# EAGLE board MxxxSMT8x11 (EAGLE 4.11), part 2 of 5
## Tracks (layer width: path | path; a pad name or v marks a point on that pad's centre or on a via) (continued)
D1  (via drill 0.61) (continued)
  Top 0.254: E16.4 94.23,12.7 96.27,10.67 96.27,9.14 97.54,9.14 E19.14 99.31,9.14 101.35,9.14 101.35,15.49 v100.33,16.51 | v80.01,15.24 81.03,15.24 E13.6 82.8,15.24 v84.07,16.51 | E10.9 65.02,15.24 v66.04,15.24 65.79,15.49 v65.79,19.56 | 46.74,12.45 50.04,12.45 50.04,11.94 50.55,11.43 E7.12 52.32,11.43 53.59,12.7 53.59,15.24 v56.13,17.78 | 46.74,12.45 44.7,12.45 E4.4 | v14.99,13.97 13.97,13.97 U$1.D1 | E1.5 30.23,13.97 v29.21,13.97 29.21,14.22 v29.21,17.27 | v46.74,17.27 46.74,12.45
  Bottom 0.254: v66.04,15.24 v80.01,15.24 | v84.07,16.51 v100.33,16.51 | v14.99,13.97 v29.21,13.97 | v46.74,17.27 46.48,17.02 29.46,17.02 v29.21,17.27 | v65.79,19.56 65.28,19.05 57.4,19.05 v56.13,17.78
D2  (via drill 0.61)
  Top 0.254: v59.69,8.64 59.69,11.18 58.67,11.18 E7.3 56.9,11.18 v55.88,11.18 | v68.58,8.64 69.6,8.64 E10.1 | v80.01,8.89 81.03,8.89 E13.1 82.8,8.64 82.8,5.08 100.08,5.08 101.85,6.86 101.85,13.72 103.89,13.72 E19.5 | v85.09,12.19 85.09,12.45 86.11,12.45 E16.11 | v29.21,12.7 30.23,12.7 E1.4 32,12.7 32.51,12.19 32.51,10.41 36.58,10.41 E4.13 38.35,10.41 38.35,10.67 v39.37,10.67
  Bottom 0.254: v59.69,8.64 v68.58,8.64 68.83,8.89 v80.01,8.89 80.26,9.14 82.04,9.14 v85.09,12.19 | v29.21,12.7 13.97,12.7 U$1.D2 | v55.88,11.18 55.37,10.67 v39.37,10.67
D3  (via drill 0.61)
  Top 0.254: v59.69,74.68 59.69,77.22 58.67,77.22 E25.3 56.9,77.22 v55.88,77.22 | v68.58,74.68 69.6,74.68 E28.1 | v80.01,74.93 81.03,74.93 E31.1 82.8,74.68 82.8,71.12 100.08,71.12 101.85,72.9 101.85,79.76 103.89,79.76 E40.5 | v85.09,78.23 85.09,78.49 86.11,78.49 E37.11 | v29.21,78.74 30.23,78.74 E34.4 32,78.74 32.51,78.23 32.51,76.45 36.58,76.45 E22.13 38.35,76.45 38.35,76.71 v39.37,76.71
  Bottom 0.254: v59.69,74.68 v68.58,74.68 68.83,74.93 v80.01,74.93 80.26,75.18 82.04,75.18 v85.09,78.23 | v29.21,78.74 13.97,78.74 U$6.D2 | v55.88,77.22 55.37,76.71 v39.37,76.71
D4  (via drill 0.61)
  Top 0.254: E37.4 94.23,78.74 96.27,76.71 96.27,75.18 97.54,75.18 E40.14 99.31,75.18 101.35,75.18 101.35,81.53 v100.33,82.55 | v80.01,81.28 81.03,81.28 E31.6 82.8,81.28 v84.07,82.55 | E28.9 65.02,81.28 v66.04,81.28 65.79,81.53 v65.79,85.6 | 46.74,78.49 50.04,78.49 50.04,77.98 50.55,77.47 E25.12 52.32,77.47 53.59,78.74 53.59,81.28 v56.13,83.82 | 46.74,78.49 44.7,78.49 E22.4 | v14.99,80.01 13.97,80.01 U$6.D1 | E34.5 30.23,80.01 v29.21,80.01 29.21,80.26 v29.21,83.31 | v46.74,83.31 46.74,78.49
  Bottom 0.254: v66.04,81.28 v80.01,81.28 | v84.07,82.55 v100.33,82.55 | v14.99,80.01 v29.21,80.01 | v46.74,83.31 46.48,83.06 29.46,83.06 v29.21,83.31 | v65.79,85.6 65.28,85.09 57.4,85.09 v56.13,83.82
D5  (via drill 0.61)
  Top 0.254: v59.69,140.72 59.69,143.26 58.67,143.26 E46.3 56.9,143.26 v55.88,143.26 | v68.58,140.72 69.6,140.72 E49.1 | v80.01,140.97 81.03,140.97 E52.1 82.8,140.72 82.8,137.16 100.08,137.16 101.85,138.94 101.85,145.8 103.89,145.8 E61.5 | v85.09,144.27 85.09,144.53 86.11,144.53 E58.11 | v29.21,144.78 30.23,144.78 E55.4 32,144.78 32.51,144.27 32.51,142.49 36.58,142.49 E43.13 38.35,142.49 38.35,142.75 v39.37,142.75
  Bottom 0.254: v59.69,140.72 v68.58,140.72 68.83,140.97 v80.01,140.97 80.26,141.22 82.04,141.22 v85.09,144.27 | v29.21,144.78 13.97,144.78 U$9.D2 | v55.88,143.26 55.37,142.75 v39.37,142.75
D6  (via drill 0.61)
  Top 0.254: E58.4 94.23,144.78 96.27,142.75 96.27,141.22 97.54,141.22 E61.14 99.31,141.22 101.35,141.22 101.35,147.57 v100.33,148.59 | v80.01,147.32 81.03,147.32 E52.6 82.8,147.32 v84.07,148.59 | E49.9 65.02,147.32 v66.04,147.32 65.79,147.57 v65.79,151.64 | 46.74,144.53 50.04,144.53 50.04,144.02 50.55,143.51 E46.12 52.32,143.51 53.59,144.78 53.59,147.32 v56.13,149.86 | 46.74,144.53 44.7,144.53 E43.4 | v14.99,146.05 13.97,146.05 U$9.D1 | E55.5 30.23,146.05 v29.21,146.05 29.21,146.3 v29.21,149.35 | v46.74,149.35 46.74,144.53
  Bottom 0.254: v66.04,147.32 v80.01,147.32 | v84.07,148.59 v100.33,148.59 | v14.99,146.05 v29.21,146.05 | v46.74,149.35 46.48,149.1 29.46,149.1 v29.21,149.35 | v65.79,151.64 65.28,151.13 57.4,151.13 v56.13,149.86
D7  (via drill 0.61)
  Top 0.254: v196.85,185.67 196.85,183.13 197.87,183.13 E67.3 199.64,183.13 v200.66,183.13 | v187.96,185.67 186.94,185.67 E70.1 | v176.53,185.42 175.51,185.42 E73.1 173.74,185.67 173.74,189.23 156.46,189.23 154.69,187.45 154.69,180.59 152.65,180.59 E82.5 | v171.45,182.12 171.45,181.86 170.43,181.86 E79.11 | v227.33,181.61 226.31,181.61 E76.4 224.54,181.61 224.03,182.12 224.03,183.9 219.96,183.9 E64.13 218.19,183.9 218.19,183.64 v217.17,183.64
  Bottom 0.254: v196.85,185.67 v187.96,185.67 187.71,185.42 v176.53,185.42 176.28,185.17 174.5,185.17 v171.45,182.12 | v227.33,181.61 242.57,181.61 U$12.D2 | v200.66,183.13 201.17,183.64 v217.17,183.64
D8  (via drill 0.61)
  Top 0.254: E79.4 162.31,181.61 160.27,183.64 160.27,185.17 159,185.17 E82.14 157.23,185.17 155.19,185.17 155.19,178.82 v156.21,177.8 | v176.53,179.07 175.51,179.07 E73.6 173.74,179.07 v172.47,177.8 | E70.9 191.52,179.07 v190.5,179.07 190.75,178.82 v190.75,174.75 | 209.8,181.86 206.5,181.86 206.5,182.37 205.99,182.88 E67.12 204.22,182.88 202.95,181.61 202.95,179.07 v200.41,176.53 | 209.8,181.86 211.84,181.86 E64.4 | v241.55,180.34 242.57,180.34 U$12.D1 | E76.5 226.31,180.34 v227.33,180.34 227.33,180.09 v227.33,177.04 | 209.8,181.86 v209.8,177.04
  Bottom 0.254: v176.53,179.07 v190.5,179.07 | v156.21,177.8 v172.47,177.8 | v227.33,180.34 v241.55,180.34 | v209.8,177.04 210.06,177.29 227.08,177.29 v227.33,177.04 | v190.75,174.75 191.26,175.26 199.14,175.26 v200.41,176.53
D9  (via drill 0.61)
  Top 0.254: v196.85,119.63 196.85,117.09 197.87,117.09 E88.3 199.64,117.09 v200.66,117.09 | v187.96,119.63 186.94,119.63 E91.1 | v176.53,119.38 175.51,119.38 E94.1 173.74,119.63 173.74,123.19 156.46,123.19 154.69,121.41 154.69,114.55 152.65,114.55 E103.5 | v171.45,116.08 171.45,115.82 170.43,115.82 E100.11 | v227.33,115.57 226.31,115.57 E97.4 224.54,115.57 224.03,116.08 224.03,117.86 219.96,117.86 E85.13 218.19,117.86 218.19,117.6 v217.17,117.6
  Bottom 0.254: v196.85,119.63 v187.96,119.63 187.71,119.38 v176.53,119.38 176.28,119.13 174.5,119.13 v171.45,116.08 | v227.33,115.57 242.57,115.57 U$15.D2 | v200.66,117.09 201.17,117.6 v217.17,117.6
D10  (via drill 0.61)
  Top 0.254: E100.4 162.31,115.57 160.27,117.6 160.27,119.13 159,119.13 E103.14 157.23,119.13 155.19,119.13 155.19,112.78 v156.21,111.76 | v176.53,113.03 175.51,113.03 E94.6 173.74,113.03 v172.47,111.76 | E91.9 191.52,113.03 v190.5,113.03 190.75,112.78 v190.75,108.71 | 209.8,115.82 206.5,115.82 206.5,116.33 205.99,116.84 E88.12 204.22,116.84 202.95,115.57 202.95,113.03 v200.41,110.49 | 209.8,115.82 211.84,115.82 E85.4 | v241.55,114.3 242.57,114.3 U$15.D1 | E97.5 226.31,114.3 v227.33,114.3 227.33,114.05 v227.33,111 | 209.8,115.82 v209.8,111
  Bottom 0.254: v176.53,113.03 v190.5,113.03 | v156.21,111.76 v172.47,111.76 | v227.33,114.3 v241.55,114.3 | v209.8,111 210.06,111.25 227.08,111.25 v227.33,111 | v190.75,108.71 191.26,109.22 199.14,109.22 v200.41,110.49
D11  (via drill 0.61)
  Top 0.254: v196.85,53.59 196.85,51.05 197.87,51.05 E109.3 199.64,51.05 v200.66,51.05 | v187.96,53.59 186.94,53.59 E112.1 | v176.53,53.34 175.51,53.34 E115.1 173.74,53.59 173.74,57.15 156.46,57.15 154.69,55.37 154.69,48.51 152.65,48.51 E124.5 | v171.45,50.04 171.45,49.78 170.43,49.78 E121.11 | v227.33,49.53 226.31,49.53 E118.4 224.54,49.53 224.03,50.04 224.03,51.82 219.96,51.82 E106.13 218.19,51.82 218.19,51.56 v217.17,51.56
  Bottom 0.254: v196.85,53.59 v187.96,53.59 187.71,53.34 v176.53,53.34 176.28,53.09 174.5,53.09 v171.45,50.04 | v227.33,49.53 242.57,49.53 U$18.D2 | v200.66,51.05 201.17,51.56 v217.17,51.56
D12  (via drill 0.61)
  Top 0.254: E121.4 162.31,49.53 160.27,51.56 160.27,53.09 159,53.09 E124.14 157.23,53.09 155.19,53.09 155.19,46.74 v156.21,45.72 | v176.53,46.99 175.51,46.99 E115.6 173.74,46.99 v172.47,45.72 | E112.9 191.52,46.99 v190.5,46.99 190.75,46.74 v190.75,42.67 | 209.8,49.78 206.5,49.78 206.5,50.29 205.99,50.8 E109.12 204.22,50.8 202.95,49.53 202.95,46.99 v200.41,44.45 | 209.8,49.78 211.84,49.78 E106.4 | v241.55,48.26 242.57,48.26 U$18.D1 | E118.5 226.31,48.26 v227.33,48.26 227.33,48.01 v227.33,44.96 | 209.8,49.78 v209.8,44.96
  Bottom 0.254: v190.5,46.99 v176.53,46.99 | v172.47,45.72 v156.21,45.72 | v227.33,48.26 v241.55,48.26 | v209.8,44.96 210.06,45.21 227.08,45.21 v227.33,44.96 | v190.75,42.67 191.26,43.18 199.14,43.18 v200.41,44.45
E1  (via drill 0.61)
  Top 0.254: v91.44,14.22 92.46,14.22 E16.5 | v100.33,13.46 100.08,13.21 100.08,12.19 99.31,11.43 E19.12 | v80.01,16.51 79.25,17.27 v79.25,18.29 | v64.52,20.07 64.52,16.76 E10.8 63.25,16.51 v62.23,16.51 | v45.72,14.22 44.7,14.22 E4.5 | v49.28,14.22 50.8,14.22 E7.10 | v35.56,11.68 33.02,14.22 33.02,15.24 32,15.24 E1.6 | v16.76,10.16 16.26,10.67 16.26,14.22 15.24,15.24 | 15.24,15.24 13.72,16.76 U$1.E1 | 15.24,15.24 v16.26,16.26
  Bottom 0.254: v100.33,13.46 99.31,14.48 91.69,14.48 v91.44,14.22 91.19,14.48 84.84,14.48 82.8,16.51 v80.01,16.51 | v79.25,18.29 77.22,20.32 66.29,20.32 66.04,20.57 65.02,20.57 v64.52,20.07 | v35.56,11.68 33.53,9.65 23.88,9.65 23.88,9.14 17.78,9.14 v16.76,10.16 | v16.26,16.26 23.88,16.26 23.88,15.75 38.61,15.75 40.13,14.22 v45.72,14.22 v49.28,14.22 49.53,14.48 50.8,15.75 61.47,15.75 v62.23,16.51
E2  (via drill 0.61)
  Top 0.254: v80.01,10.16 81.03,10.16 E13.2 82.8,10.16 83.31,10.67 83.31,11.18 86.11,11.18 E16.12 87.88,11.43 88.65,12.19 88.65,12.7 90.93,14.99 90.93,17.78 90.68,18.03 90.68,22.1 90.93,22.35 90.93,24.13 92.96,24.13 93.98,23.11 93.98,19.56 97.03,16.51 97.03,14.22 97.54,14.22 E19.10 | E10.2 69.6,10.16 v68.58,10.16 68.33,10.41 67.31,11.43 v67.31,12.19 | v39.37,11.94 39.37,11.68 38.35,11.68 E4.12 | v55.88,12.45 56.9,12.45 E7.4 | v22.86,15.24 23.88,15.24 E1.9
  Bottom 0.254: v68.58,10.16 v80.01,10.16 | U$1.E2 13.97,16.26 14.99,16.26 16,15.24 v22.86,15.24 29.21,15.24 30.48,13.97 37.34,13.97 v39.37,11.94 39.62,12.19 55.63,12.19 v55.88,12.45 56.13,12.19 v67.31,12.19
E3  (via drill 0.61)
  Top 0.254: v80.01,76.2 81.03,76.2 E31.2 82.8,76.2 83.31,76.71 83.31,77.22 86.11,77.22 E37.12 87.88,77.47 88.65,78.23 88.65,78.74 90.93,81.03 90.93,83.82 90.68,84.07 90.68,88.14 90.93,88.39 90.93,90.17 92.96,90.17 93.98,89.15 93.98,85.6 97.03,82.55 97.03,80.26 97.54,80.26 E40.10 | E28.2 69.6,76.2 v68.58,76.2 68.33,76.45 67.31,77.47 v67.31,78.23 | v39.37,77.98 39.37,77.72 38.35,77.72 E22.12 | v55.88,78.49 56.9,78.49 E25.4 | v22.86,81.28 23.88,81.28 E34.9
  Bottom 0.254: v68.58,76.2 v80.01,76.2 | U$6.E2 13.97,82.3 14.99,82.3 16,81.28 v22.86,81.28 29.21,81.28 30.48,80.01 37.34,80.01 v39.37,77.98 39.62,78.23 55.63,78.23 v55.88,78.49 56.13,78.23 v67.31,78.23
E4  (via drill 0.61)
  Top 0.254: v91.44,80.26 92.46,80.26 E37.5 | v100.33,79.5 100.08,79.25 100.08,78.23 99.31,77.47 E40.12 | v80.01,82.55 79.25,83.31 v79.25,84.33 | v64.52,86.11 64.52,82.8 E28.8 63.25,82.55 v62.23,82.55 | v45.72,80.26 44.7,80.26 E22.5 | v49.28,80.26 50.8,80.26 E25.10 | v35.56,77.72 33.02,80.26 33.02,81.28 32,81.28 E34.6 | v16.76,76.2 16.26,76.71 16.26,80.26 15.24,81.28 | 15.24,81.28 13.72,82.8 U$6.E1 | 15.24,81.28 v16.26,82.3
  Bottom 0.254: v100.33,79.5 99.31,80.52 91.69,80.52 v91.44,80.26 91.19,80.52 84.84,80.52 82.8,82.55 v80.01,82.55 | v79.25,84.33 77.22,86.36 66.29,86.36 66.04,86.61 65.02,86.61 v64.52,86.11 | v35.56,77.72 33.53,75.69 23.88,75.69 23.88,75.18 17.78,75.18 v16.76,76.2 | v16.26,82.3 23.88,82.3 23.88,81.79 38.61,81.79 40.13,80.26 v45.72,80.26 v49.28,80.26 49.53,80.52 50.8,81.79 61.47,81.79 v62.23,82.55
E5  (via drill 0.61)
  Top 0.254: v80.01,142.24 81.03,142.24 E52.2 82.8,142.24 83.31,142.75 83.31,143.26 86.11,143.26 E58.12 87.88,143.51 88.65,144.27 88.65,144.78 90.93,147.07 90.93,149.86 90.68,150.11 90.68,154.18 90.93,154.43 90.93,156.21 92.96,156.21 93.98,155.19 93.98,151.64 97.03,148.59 97.03,146.3 97.54,146.3 E61.10 | E49.2 69.6,142.24 v68.58,142.24 68.33,142.49 67.31,143.51 v67.31,144.27 | v39.37,144.02 39.37,143.76 38.35,143.76 E43.12 | v55.88,144.53 56.9,144.53 E46.4 | v22.86,147.32 23.88,147.32 E55.9
  Bottom 0.254: v68.58,142.24 v80.01,142.24 | U$9.E2 13.97,148.34 14.99,148.34 16,147.32 v22.86,147.32 29.21,147.32 30.48,146.05 37.34,146.05 v39.37,144.02 39.62,144.27 55.63,144.27 v55.88,144.53 56.13,144.27 v67.31,144.27
E6  (via drill 0.61)
  Top 0.254: v91.44,146.3 92.46,146.3 E58.5 | v100.33,145.54 100.08,145.29 100.08,144.27 99.31,143.51 E61.12 | v80.01,148.59 79.25,149.35 v79.25,150.37 | v64.52,152.15 64.52,148.84 E49.8 63.25,148.59 v62.23,148.59 | v45.72,146.3 44.7,146.3 E43.5 | v49.28,146.3 50.8,146.3 E46.10 | v35.56,143.76 33.02,146.3 33.02,147.32 32,147.32 E55.6 | v16.76,142.24 16.26,142.75 16.26,146.3 15.24,147.32 | 15.24,147.32 13.72,148.84 U$9.E1 | 15.24,147.32 v16.26,148.34
  Bottom 0.254: v100.33,145.54 99.31,146.56 91.69,146.56 v91.44,146.3 91.19,146.56 84.84,146.56 82.8,148.59 v80.01,148.59 | v79.25,150.37 77.22,152.4 66.29,152.4 66.04,152.65 65.02,152.65 v64.52,152.15 | v35.56,143.76 33.53,141.73 23.88,141.73 23.88,141.22 17.78,141.22 v16.76,142.24 | v16.26,148.34 23.88,148.34 23.88,147.83 38.61,147.83 40.13,146.3 v45.72,146.3 v49.28,146.3 49.53,146.56 50.8,147.83 61.47,147.83 v62.23,148.59
E7  (via drill 0.61)
  Top 0.254: v176.53,184.15 175.51,184.15 E73.2 173.74,184.15 173.23,183.64 173.23,183.13 170.43,183.13 E79.12 168.66,182.88 167.89,182.12 167.89,181.61 165.61,179.32 165.61,176.53 165.86,176.28 165.86,172.21 165.61,171.96 165.61,170.18 163.58,170.18 162.56,171.2 162.56,174.75 159.51,177.8 159.51,180.09 159,180.09 E82.10 | E70.2 186.94,184.15 v187.96,184.15 188.21,183.9 189.23,182.88 v189.23,182.12 | v217.17,182.37 217.17,182.63 218.19,182.63 E64.12 | v200.66,181.86 199.64,181.86 E67.4 | v233.68,179.07 232.66,179.07 E76.9
  Bottom 0.254: v176.53,184.15 v187.96,184.15 | U$12.E2 242.57,178.05 241.55,178.05 240.54,179.07 v233.68,179.07 227.33,179.07 226.06,180.34 219.2,180.34 v217.17,182.37 216.92,182.12 200.91,182.12 v200.66,181.86 200.41,182.12 v189.23,182.12
E8  (via drill 0.61)
  Top 0.254: v165.1,180.09 164.08,180.09 E79.5 | v156.21,180.85 156.46,181.1 156.46,182.12 157.23,182.88 E82.12 | v176.53,177.8 177.29,177.04 v177.29,176.02 | v192.02,174.24 192.02,177.55 E70.8 193.29,177.8 v194.31,177.8 | v210.82,180.09 211.84,180.09 E64.5 | v207.26,180.09 205.74,180.09 E67.10 | v220.98,182.63 223.52,180.09 223.52,179.07 224.54,179.07 E76.6 | v239.78,184.15 240.28,183.64 240.28,180.09 241.3,179.07 | 241.3,179.07 242.82,177.55 U$12.E1 | v240.28,178.05 241.3,179.07
  Bottom 0.254: v156.21,180.85 157.23,179.83 164.85,179.83 v165.1,180.09 165.35,179.83 171.7,179.83 173.74,177.8 v176.53,177.8 | v177.29,176.02 179.32,173.99 190.25,173.99 190.5,173.74 191.52,173.74 v192.02,174.24 | v220.98,182.63 223.01,184.66 232.66,184.66 232.66,185.17 238.76,185.17 v239.78,184.15 | v240.28,178.05 232.66,178.05 232.66,178.56 217.93,178.56 216.41,180.09 v210.82,180.09 v207.26,180.09 207.01,179.83 205.74,178.56 195.07,178.56 v194.31,177.8
E9  (via drill 0.61)
  Top 0.254: v176.53,118.11 175.51,118.11 E94.2 173.74,118.11 173.23,117.6 173.23,117.09 170.43,117.09 E100.12 168.66,116.84 167.89,116.08 167.89,115.57 165.61,113.28 165.61,110.49 165.86,110.24 165.86,106.17 165.61,105.92 165.61,104.14 163.58,104.14 162.56,105.16 162.56,108.71 159.51,111.76 159.51,114.05 159,114.05 E103.10 | E91.2 186.94,118.11 v187.96,118.11 188.21,117.86 189.23,116.84 v189.23,116.08 | v217.17,116.33 217.17,116.59 218.19,116.59 E85.12 | v200.66,115.82 199.64,115.82 E88.4 | v233.68,113.03 232.66,113.03 E97.9
  Bottom 0.254: v176.53,118.11 v187.96,118.11 | U$15.E2 242.57,112.01 241.55,112.01 240.54,113.03 v233.68,113.03 227.33,113.03 226.06,114.3 219.2,114.3 v217.17,116.33 216.92,116.08 200.91,116.08 v200.66,115.82 200.41,116.08 v189.23,116.08
E10  (via drill 0.61)
  Top 0.254: v165.1,114.05 164.08,114.05 E100.5 | v156.21,114.81 156.46,115.06 156.46,116.08 157.23,116.84 E103.12 | v176.53,111.76 177.29,111 v177.29,109.98 | v192.02,108.2 192.02,111.51 E91.8 193.29,111.76 v194.31,111.76 | v210.82,114.05 211.84,114.05 E85.5 | v207.26,114.05 205.74,114.05 E88.10 | v220.98,116.59 223.52,114.05 223.52,113.03 224.54,113.03 E97.6 | v239.78,118.11 240.28,117.6 240.28,114.05 241.3,113.03 | 241.3,113.03 242.82,111.51 U$15.E1 | v240.28,112.01 241.3,113.03
  Bottom 0.254: v156.21,114.81 157.23,113.79 164.85,113.79 v165.1,114.05 165.35,113.79 171.7,113.79 173.74,111.76 v176.53,111.76 | v177.29,109.98 179.32,107.95 190.25,107.95 190.5,107.7 191.52,107.7 v192.02,108.2 | v220.98,116.59 223.01,118.62 232.66,118.62 232.66,119.13 238.76,119.13 v239.78,118.11 | v240.28,112.01 232.66,112.01 232.66,112.52 217.93,112.52 216.41,114.05 v210.82,114.05 v207.26,114.05 207.01,113.79 205.74,112.52 195.07,112.52 v194.31,111.76
E11  (via drill 0.61)
  Top 0.254: v176.53,52.07 175.51,52.07 E115.2 173.74,52.07 173.23,51.56 173.23,51.05 170.43,51.05 E121.12 168.66,50.8 167.89,50.04 167.89,49.53 165.61,47.24 165.61,44.45 165.86,44.2 165.86,40.13 165.61,39.88 165.61,38.1 163.58,38.1 162.56,39.12 162.56,42.67 159.51,45.72 159.51,48.01 159,48.01 E124.10 | E112.2 186.94,52.07 v187.96,52.07 188.21,51.82 189.23,50.8 v189.23,50.04 | v217.17,50.29 217.17,50.55 218.19,50.55 E106.12 | v200.66,49.78 199.64,49.78 E109.4 | v233.68,46.99 232.66,46.99 E118.9
  Bottom 0.254: v187.96,52.07 v176.53,52.07 | U$18.E2 242.57,45.97 241.55,45.97 240.54,46.99 v233.68,46.99 227.33,46.99 226.06,48.26 219.2,48.26 v217.17,50.29 216.92,50.04 200.91,50.04 v200.66,49.78 200.41,50.04 v189.23,50.04
E12  (via drill 0.61)
  Top 0.254: v165.1,48.01 164.08,48.01 E121.5 | v156.21,48.77 156.46,49.02 156.46,50.04 157.23,50.8 E124.12 | v176.53,45.72 177.29,44.96 v177.29,43.94 | v192.02,42.16 192.02,45.47 E112.8 193.29,45.72 v194.31,45.72 | v210.82,48.01 211.84,48.01 E106.5 | v207.26,48.01 205.74,48.01 E109.10 | v220.98,50.55 223.52,48.01 223.52,46.99 224.54,46.99 E118.6 | v239.78,52.07 240.28,51.56 240.28,48.01 241.3,46.99 | 241.3,46.99 242.82,45.47 U$18.E1 | v240.28,45.97 241.3,46.99
  Bottom 0.254: v156.21,48.77 157.23,47.75 164.85,47.75 v165.1,48.01 165.35,47.75 171.7,47.75 173.74,45.72 v176.53,45.72 | v177.29,43.94 179.32,41.91 190.25,41.91 190.5,41.66 191.52,41.66 v192.02,42.16 | v220.98,50.55 223.01,52.58 232.66,52.58 232.66,53.09 238.76,53.09 v239.78,52.07 | v240.28,45.97 232.66,45.97 232.66,46.48 217.93,46.48 216.41,48.01 v210.82,48.01 v207.26,48.01 207.01,47.75 205.74,46.48 195.07,46.48 v194.31,45.72
F1  (via drill 0.61)
  Top 0.254: 15.75,20.57 13.97,20.57 U$1.F1 | 15.75,20.57 18.03,20.57 21.34,17.27 21.34,12.95 23.88,12.95 E1.11 | E19.13 97.54,10.16 97.03,10.67 97.03,11.68 94.74,13.97 94.74,14.99 94.23,14.99 E16.6 92.46,15.49 91.69,15.49 v91.69,21.84 | 48.77,18.29 v47.75,18.29 46.48,18.29 45.72,17.53 45.72,15.49 44.7,15.49 E4.6 | 48.77,18.29 48.77,17.02 50.55,15.24 E7.9 | v77.47,25.65 77.22,25.91 77.22,27.18 76.45,27.94 E14.12 | E11.13 65.02,26.42 v66.04,26.42 66.04,26.16 66.04,21.59 64.77,21.59 v63.25,20.07 | 48.77,18.29 v49.53,19.05 | v24.38,4.06 22.35,6.1 22.35,9.14 18.8,9.14 17.78,10.16 17.78,16.26 15.75,18.29 15.75,20.32 15.75,20.57 | v42.16,2.03 40.64,3.56 40.64,14.73 40.13,15.24 40.13,16.76 v41.66,18.29 | v109.98,15.75 110.24,15.49 110.24,7.11 v108.97,5.84
  Bottom 0.254: v66.04,26.42 66.29,26.16 70.87,26.16 72.39,24.64 73.91,24.64 74.93,25.65 v77.47,25.65 | v49.53,19.05 50.29,19.81 62.99,19.81 v63.25,20.07 | v24.38,4.06 26.42,2.03 v42.16,2.03 42.42,2.03 105.16,2.03 v108.97,5.84 | v41.66,18.29 v47.75,18.29 | v91.69,21.84 91.95,21.59 101.35,21.59 103.89,24.13 104.39,24.13 109.98,18.54 v109.98,15.75
F2  (via drill 0.61)
  Top 0.254: v59.69,13.46 59.69,13.72 58.67,13.72 E7.5 | v68.58,12.95 69.6,12.95 E10.4 | v103.12,17.53 103.89,16.76 E19.7 | v89.92,17.53 89.92,15.24 88.9,14.22 87.88,14.22 E16.10 86.11,13.72 85.34,13.72 84.07,12.45 84.07,11.68 82.8,11.68 E13.3 81.03,11.18 v80.01,12.19 | v39.12,18.03 39.12,13.46 | 39.12,13.46 39.12,12.95 38.35,12.95 E4.11 | v23.37,17.53 23.37,17.27 23.88,16.76 E1.8 | 39.12,13.46 v39.37,13.46
  Bottom 0.254: v89.92,17.53 v103.12,17.53 | v80.01,12.19 69.34,12.19 68.83,12.7 v68.58,12.95 68.33,13.21 59.94,13.21 v59.69,13.46 59.44,13.72 50.55,13.72 49.78,12.95 39.88,12.95 v39.37,13.46 | v39.12,18.03 38.61,18.54 23.37,18.54 | 23.37,18.54 15.75,18.54 15.24,19.05 13.97,19.05 U$1.F2 | 23.37,18.54 v23.37,17.53
F3  (via drill 0.61)
  Top 0.254: v59.69,79.5 59.69,79.76 58.67,79.76 E25.5 | v68.58,78.99 69.6,78.99 E28.4 | v103.12,83.57 103.89,82.8 E40.7 | v89.92,83.57 89.92,81.28 88.9,80.26 87.88,80.26 E37.10 86.11,79.76 85.34,79.76 84.07,78.49 84.07,77.72 82.8,77.72 E31.3 81.03,77.22 v80.01,78.23 | v39.12,84.07 39.12,79.5 | 39.12,79.5 39.12,78.99 38.35,78.99 E22.11 | v23.37,83.57 23.37,83.31 23.88,82.8 E34.8 | 39.12,79.5 v39.37,79.5
  Bottom 0.254: v89.92,83.57 v103.12,83.57 | v80.01,78.23 69.34,78.23 68.83,78.74 v68.58,78.99 68.33,79.25 59.94,79.25 v59.69,79.5 59.44,79.76 50.55,79.76 49.78,78.99 39.88,78.99 v39.37,79.5 | v39.12,84.07 38.61,84.58 23.37,84.58 | 23.37,84.58 15.75,84.58 15.24,85.09 13.97,85.09 U$6.F2 | 23.37,84.58 v23.37,83.57
F4  (via drill 0.61)
  Top 0.254: 15.75,86.61 13.97,86.61 U$6.F1 | 15.75,86.61 18.03,86.61 21.34,83.31 21.34,78.99 23.88,78.99 E34.11 | E40.13 97.54,76.2 97.03,76.71 97.03,77.72 94.74,80.01 94.74,81.03 94.23,81.03 E37.6 92.46,81.53 91.69,81.53 v91.69,87.88 | 48.77,84.33 v47.75,84.33 46.48,84.33 45.72,83.57 45.72,81.53 44.7,81.53 E22.6 | 48.77,84.33 48.77,83.06 50.55,81.28 E25.9 | v77.47,91.69 77.22,91.95 77.22,93.22 76.45,93.98 E32.12 | E29.13 65.02,92.46 v66.04,92.46 66.04,92.2 66.04,87.63 64.77,87.63 v63.25,86.11 | 48.77,84.33 v49.53,85.09 | v24.38,70.1 22.35,72.14 22.35,75.18 18.8,75.18 17.78,76.2 17.78,82.3 15.75,84.33 15.75,86.36 15.75,86.61 | v42.16,68.07 40.64,69.6 40.64,80.77 40.13,81.28 40.13,82.8 v41.66,84.33 | v109.98,81.79 110.24,81.53 110.24,73.15 v108.97,71.88
  Bottom 0.254: v66.04,92.46 66.29,92.2 70.87,92.2 72.39,90.68 73.91,90.68 74.93,91.69 v77.47,91.69 | v49.53,85.09 50.29,85.85 62.99,85.85 v63.25,86.11 | v24.38,70.1 26.42,68.07 v42.16,68.07 42.42,68.07 105.16,68.07 v108.97,71.88 | v41.66,84.33 v47.75,84.33 | v91.69,87.88 91.95,87.63 101.35,87.63 103.89,90.17 104.39,90.17 109.98,84.58 v109.98,81.79
F5  (via drill 0.61)
  Top 0.254: v59.69,145.54 59.69,145.8 58.67,145.8 E46.5 | v68.58,145.03 69.6,145.03 E49.4 | v103.12,149.61 103.89,148.84 E61.7 | v89.92,149.61 89.92,147.32 88.9,146.3 87.88,146.3 E58.10 86.11,145.8 85.34,145.8 84.07,144.53 84.07,143.76 82.8,143.76 E52.3 81.03,143.26 v80.01,144.27 | v39.12,150.11 39.12,145.54 | 39.12,145.54 39.12,145.03 38.35,145.03 E43.11 | v23.37,149.61 23.37,149.35 23.88,148.84 E55.8 | 39.12,145.54 v39.37,145.54
  Bottom 0.254: v89.92,149.61 v103.12,149.61 | v80.01,144.27 69.34,144.27 68.83,144.78 v68.58,145.03 68.33,145.29 59.94,145.29 v59.69,145.54 59.44,145.8 50.55,145.8 49.78,145.03 39.88,145.03 v39.37,145.54 | v39.12,150.11 38.61,150.62 23.37,150.62 | 23.37,150.62 15.75,150.62 15.24,151.13 13.97,151.13 U$9.F2 | 23.37,150.62 v23.37,149.61
F6  (via drill 0.61)
  Top 0.254: 15.75,152.65 13.97,152.65 U$9.F1 | 15.75,152.65 18.03,152.65 21.34,149.35 21.34,145.03 23.88,145.03 E55.11 | E61.13 97.54,142.24 97.03,142.75 97.03,143.76 94.74,146.05 94.74,147.07 94.23,147.07 E58.6 92.46,147.57 91.69,147.57 v91.69,153.92 | 48.77,150.37 v47.75,150.37 46.48,150.37 45.72,149.61 45.72,147.57 44.7,147.57 E43.6 | 48.77,150.37 48.77,149.1 50.55,147.32 E46.9 | v77.47,157.73 77.22,157.99 77.22,159.26 76.45,160.02 E53.12 | E50.13 65.02,158.5 v66.04,158.5 66.04,158.24 66.04,153.67 64.77,153.67 v63.25,152.15 | 48.77,150.37 v49.53,151.13 | v24.38,136.14 22.35,138.18 22.35,141.22 18.8,141.22 17.78,142.24 17.78,148.34 15.75,150.37 15.75,152.4 15.75,152.65 | v42.16,134.11 40.64,135.64 40.64,146.81 40.13,147.32 40.13,148.84 v41.66,150.37 | v109.98,147.83 110.24,147.57 110.24,139.19 v108.97,137.92
  Bottom 0.254: v66.04,158.5 66.29,158.24 70.87,158.24 72.39,156.72 73.91,156.72 74.93,157.73 v77.47,157.73 | v49.53,151.13 50.29,151.89 62.99,151.89 v63.25,152.15 | v24.38,136.14 26.42,134.11 v42.16,134.11 42.42,134.11 105.16,134.11 v108.97,137.92 | v41.66,150.37 v47.75,150.37 | v91.69,153.92 91.95,153.67 101.35,153.67 103.89,156.21 104.39,156.21 109.98,150.62 v109.98,147.83
F7  (via drill 0.61)
  Top 0.254: v196.85,180.85 196.85,180.59 197.87,180.59 E67.5 | v187.96,181.36 186.94,181.36 E70.4 | v153.42,176.78 152.65,177.55 E82.7 | v166.62,176.78 166.62,179.07 167.64,180.09 168.66,180.09 E79.10 170.43,180.59 171.2,180.59 172.47,181.86 172.47,182.63 173.74,182.63 E73.3 175.51,183.13 v176.53,182.12 | 217.42,180.85 v217.42,176.28 | 217.42,180.85 217.42,181.36 218.19,181.36 E64.11 | v233.17,176.78 233.17,177.04 232.66,177.55 E76.8 | v217.17,180.85 217.42,180.85
  Bottom 0.254: v153.42,176.78 v166.62,176.78 | v176.53,182.12 187.2,182.12 187.71,181.61 v187.96,181.36 188.21,181.1 196.6,181.1 v196.85,180.85 197.1,180.59 205.99,180.59 206.76,181.36 216.66,181.36 v217.17,180.85 | v217.42,176.28 217.93,175.77 233.17,175.77 | 233.17,175.77 240.79,175.77 241.3,175.26 242.57,175.26 U$12.F2 | 233.17,175.77 v233.17,176.78
F8  (via drill 0.61)
  Top 0.254: 240.79,173.74 242.57,173.74 U$12.F1 | 240.79,173.74 238.51,173.74 235.2,177.04 235.2,181.36 232.66,181.36 E76.11 | E82.13 159,184.15 159.51,183.64 159.51,182.63 161.8,180.34 161.8,179.32 162.31,179.32 E79.6 164.08,178.82 164.85,178.82 v164.85,172.47 | 207.77,176.02 v208.79,176.02 210.06,176.02 210.82,176.78 210.82,178.82 211.84,178.82 E64.6 | 207.77,176.02 207.77,177.29 205.99,179.07 E67.9 | v179.07,168.66 179.32,168.4 179.32,167.13 180.09,166.37 E74.12 | E71.13 191.52,167.89 v190.5,167.89 190.5,168.15 190.5,172.72 191.77,172.72 v193.29,174.24 | 207.77,176.02 v207.01,175.26 | v232.16,190.25 234.19,188.21 234.19,185.17 237.74,185.17 238.76,184.15 238.76,178.05 240.79,176.02 240.79,173.99 240.79,173.74 | v214.38,192.28 215.9,190.75 215.9,179.58 216.41,179.07 216.41,177.55 v214.88,176.02 | v146.56,178.56 146.3,178.82 146.3,187.2 v147.57,188.47
  Bottom 0.254: v190.5,167.89 190.25,168.15 185.67,168.15 184.15,169.67 182.63,169.67 181.61,168.66 v179.07,168.66 | v207.01,175.26 206.25,174.5 193.55,174.5 v193.29,174.24 | v232.16,190.25 230.12,192.28 v214.38,192.28 214.12,192.28 151.38,192.28 v147.57,188.47 | v214.88,176.02 v208.79,176.02 | v164.85,172.47 164.59,172.72 155.19,172.72 152.65,170.18 152.15,170.18 146.56,175.77 v146.56,178.56
F9  (via drill 0.61)
  Top 0.254: v196.85,114.81 196.85,114.55 197.87,114.55 E88.5 | v187.96,115.32 186.94,115.32 E91.4 | v153.42,110.74 152.65,111.51 E103.7 | v166.62,110.74 166.62,113.03 167.64,114.05 168.66,114.05 E100.10 170.43,114.55 171.2,114.55 172.47,115.82 172.47,116.59 173.74,116.59 E94.3 175.51,117.09 v176.53,116.08 | 217.42,114.81 v217.42,110.24 | 217.42,114.81 217.42,115.32 218.19,115.32 E85.11 | v233.17,110.74 233.17,111 232.66,111.51 E97.8 | v217.17,114.81 217.42,114.81
  Bottom 0.254: v153.42,110.74 v166.62,110.74 | v176.53,116.08 187.2,116.08 187.71,115.57 v187.96,115.32 188.21,115.06 196.6,115.06 v196.85,114.81 197.1,114.55 205.99,114.55 206.76,115.32 216.66,115.32 v217.17,114.81 | v217.42,110.24 217.93,109.73 233.17,109.73 | 233.17,109.73 240.79,109.73 241.3,109.22 242.57,109.22 U$15.F2 | 233.17,109.73 v233.17,110.74
F10  (via drill 0.61)
  Top 0.254: 240.79,107.7 242.57,107.7 U$15.F1 | 240.79,107.7 238.51,107.7 235.2,111 235.2,115.32 232.66,115.32 E97.11 | E103.13 159,118.11 159.51,117.6 159.51,116.59 161.8,114.3 161.8,113.28 162.31,113.28 E100.6 164.08,112.78 164.85,112.78 v164.85,106.43 | 207.77,109.98 v208.79,109.98 210.06,109.98 210.82,110.74 210.82,112.78 211.84,112.78 E85.6 | 207.77,109.98 207.77,111.25 205.99,113.03 E88.9 | v179.07,102.62 179.32,102.36 179.32,101.09 180.09,100.33 E95.12 | E92.13 191.52,101.85 v190.5,101.85 190.5,102.11 190.5,106.68 191.77,106.68 v193.29,108.2 | 207.77,109.98 v207.01,109.22 | v232.16,124.21 234.19,122.17 234.19,119.13 237.74,119.13 238.76,118.11 238.76,112.01 240.79,109.98 240.79,107.95 240.79,107.7 | v214.38,126.24 215.9,124.71 215.9,113.54 216.41,113.03 216.41,111.51 v214.88,109.98 | v146.56,112.52 146.3,112.78 146.3,121.16 v147.57,122.43
  Bottom 0.254: v190.5,101.85 190.25,102.11 185.67,102.11 184.15,103.63 182.63,103.63 181.61,102.62 v179.07,102.62 | v207.01,109.22 206.25,108.46 193.55,108.46 v193.29,108.2 | v232.16,124.21 230.12,126.24 v214.38,126.24 214.12,126.24 151.38,126.24 v147.57,122.43 | v214.88,109.98 v208.79,109.98 | v164.85,106.43 164.59,106.68 155.19,106.68 152.65,104.14 152.15,104.14 146.56,109.73 v146.56,112.52
F11  (via drill 0.61)
  Top 0.254: v196.85,48.77 196.85,48.51 197.87,48.51 E109.5 | v187.96,49.28 186.94,49.28 E112.4 | v153.42,44.7 152.65,45.47 E124.7 | v166.62,44.7 166.62,46.99 167.64,48.01 168.66,48.01 E121.10 170.43,48.51 171.2,48.51 172.47,49.78 172.47,50.55 173.74,50.55 E115.3 175.51,51.05 v176.53,50.04 | 217.42,48.77 v217.42,44.2 | 217.42,48.77 217.42,49.28 218.19,49.28 E106.11 | v233.17,44.7 233.17,44.96 232.66,45.47 E118.8 | v217.17,48.77 217.42,48.77
  Bottom 0.254: v166.62,44.7 v153.42,44.7 | v176.53,50.04 187.2,50.04 187.71,49.53 v187.96,49.28 188.21,49.02 196.6,49.02 v196.85,48.77 197.1,48.51 205.99,48.51 206.76,49.28 216.66,49.28 v217.17,48.77 | v217.42,44.2 217.93,43.69 233.17,43.69 | 233.17,43.69 240.79,43.69 241.3,43.18 242.57,43.18 U$18.F2 | 233.17,43.69 v233.17,44.7
F12  (via drill 0.61)
  Top 0.254: 240.79,41.66 242.57,41.66 U$18.F1 | 240.79,41.66 238.51,41.66 235.2,44.96 235.2,49.28 232.66,49.28 E118.11 | E124.13 159,52.07 159.51,51.56 159.51,50.55 161.8,48.26 161.8,47.24 162.31,47.24 E121.6 164.08,46.74 164.85,46.74 v164.85,40.39 | 207.77,43.94 v208.79,43.94 210.06,43.94 210.82,44.7 210.82,46.74 211.84,46.74 E106.6 | 207.77,43.94 207.77,45.21 205.99,46.99 E109.9 | v179.07,36.58 179.32,36.32 179.32,35.05 180.09,34.29 E116.12 | E113.13 191.52,35.81 v190.5,35.81 190.5,36.07 190.5,40.64 191.77,40.64 v193.29,42.16 | 207.77,43.94 v207.01,43.18 | v232.16,58.17 234.19,56.13 234.19,53.09 237.74,53.09 238.76,52.07 238.76,45.97 240.79,43.94 240.79,41.91 240.79,41.66 | v214.38,60.2 215.9,58.67 215.9,47.5 216.41,46.99 216.41,45.47 v214.88,43.94 | v146.56,46.48 146.3,46.74 146.3,55.12 v147.57,56.39
  Bottom 0.254: v190.5,35.81 190.25,36.07 185.67,36.07 184.15,37.59 182.63,37.59 181.61,36.58 v179.07,36.58 | v207.01,43.18 206.25,42.42 193.55,42.42 v193.29,42.16 | v232.16,58.17 230.12,60.2 v214.38,60.2 214.12,60.2 151.38,60.2 v147.57,56.39 | v208.79,43.94 v214.88,43.94 | v164.85,40.39 164.59,40.64 155.19,40.64 152.65,38.1 152.15,38.1 146.56,43.69 v146.56,46.48
FF1  (via drill 0.61)
  Top 0.254: FF1.1 96.27,57.91 96.27,58.93 J1.2 97.28,59.94 97.79,59.94 98.3,60.45 99.82,60.45 v99.82,59.94 | v91.44,8.64 90.42,9.65 90.42,10.16 87.88,10.16 E16.13 | v102.87,14.73 103.89,14.73 103.89,14.99 E19.6
  Bottom 0.254: v91.44,8.64 92.2,7.87 103.38,7.87 104.39,8.89 109.47,8.89 110.24,9.65 110.24,14.73 | 110.24,14.73 v102.87,14.73 | v99.82,59.94 100.84,58.93 108.97,58.93 111.25,56.64 111.25,14.73 110.24,14.73
FF2  (via drill 0.61)
  Top 0.254: 103.12,25.91 103.89,26.67 E20.2 | 103.12,25.91 102.62,25.4 102.62,24.64 99.31,24.64 98.55,23.88 95.5,23.88 94.23,25.15 E17.1 | v101.09,50.29 101.85,49.53 101.85,27.18 103.12,25.91
  Bottom 0.254: J2.2 95.76,54.36 91.95,54.36 91.95,52.07 92.71,51.31 95.25,51.31 95.76,51.82 FF2.1 97.28,51.82 98.81,50.29 v101.09,50.29
FF3  (via drill 0.61)
  Top 0.254: FF3.1 96.27,123.95 96.27,124.97 J3.2 97.28,125.98 97.79,125.98 98.3,126.49 99.82,126.49 v99.82,125.98 | v91.44,74.68 90.42,75.69 90.42,76.2 87.88,76.2 E37.13 | v102.87,80.77 103.89,80.77 103.89,81.03 E40.6
  Bottom 0.254: v91.44,74.68 92.2,73.91 103.38,73.91 104.39,74.93 109.47,74.93 110.24,75.69 110.24,80.77 | 110.24,80.77 v102.87,80.77 | v99.82,125.98 100.84,124.97 108.97,124.97 111.25,122.68 111.25,80.77 110.24,80.77
FF4  (via drill 0.61)
  Top 0.254: 103.12,91.95 103.89,92.71 E41.2 | 103.12,91.95 102.62,91.44 102.62,90.68 99.31,90.68 98.55,89.92 95.5,89.92 94.23,91.19 E38.1 | v101.09,116.33 101.85,115.57 101.85,93.22 103.12,91.95
  Bottom 0.254: J4.2 95.76,120.4 91.95,120.4 91.95,118.11 92.71,117.35 95.25,117.35 95.76,117.86 FF4.1 97.28,117.86 98.81,116.33 v101.09,116.33
FF5  (via drill 0.61)
  Top 0.254: FF5.1 96.27,189.99 96.27,191.01 J5.2 97.28,192.02 97.79,192.02 98.3,192.53 99.82,192.53 v99.82,192.02 | v91.44,140.72 90.42,141.73 90.42,142.24 87.88,142.24 E58.13 | v102.87,146.81 103.89,146.81 103.89,147.07 E61.6
  Bottom 0.254: v91.44,140.72 92.2,139.95 103.38,139.95 104.39,140.97 109.47,140.97 110.24,141.73 110.24,146.81 | 110.24,146.81 v102.87,146.81 | v99.82,192.02 100.84,191.01 108.97,191.01 111.25,188.72 111.25,146.81 110.24,146.81
FF6  (via drill 0.61)
  Top 0.254: 103.12,157.99 103.89,158.75 E62.2 | 103.12,157.99 102.62,157.48 102.62,156.72 99.31,156.72 98.55,155.96 95.5,155.96 94.23,157.23 E59.1 | v101.09,182.37 101.85,181.61 101.85,159.26 103.12,157.99
  Bottom 0.254: J6.2 95.76,186.44 91.95,186.44 91.95,184.15 92.71,183.39 95.25,183.39 95.76,183.9 FF6.1 97.28,183.9 98.81,182.37 v101.09,182.37
FF7  (via drill 0.61)
  Top 0.254: FF7.1 160.27,136.4 160.27,135.38 J7.2 159.26,134.37 158.75,134.37 158.24,133.86 156.72,133.86 v156.72,134.37 | v165.1,185.67 166.12,184.66 166.12,184.15 168.66,184.15 E79.13 | v153.67,179.58 152.65,179.58 152.65,179.32 E82.6
  Bottom 0.254: v165.1,185.67 164.34,186.44 153.16,186.44 152.15,185.42 147.07,185.42 146.3,184.66 146.3,179.58 | 146.3,179.58 v153.67,179.58 | v156.72,134.37 155.7,135.38 147.57,135.38 145.29,137.67 145.29,179.58 146.3,179.58
FF8  (via drill 0.61)
  Top 0.254: 153.42,168.4 152.65,167.64 E83.2 | 153.42,168.4 153.92,168.91 153.92,169.67 157.23,169.67 157.99,170.43 161.04,170.43 162.31,169.16 E80.1 | v155.45,144.02 154.69,144.78 154.69,167.13 153.42,168.4
  Bottom 0.254: J8.2 160.78,139.95 164.59,139.95 164.59,142.24 163.83,143 161.29,143 160.78,142.49 FF8.1 159.26,142.49 157.73,144.02 v155.45,144.02
FF9  (via drill 0.61)
  Top 0.254: FF9.1 160.27,70.36 160.27,69.34 J9.2 159.26,68.33 158.75,68.33 158.24,67.82 156.72,67.82 v156.72,68.33 | v165.1,119.63 166.12,118.62 166.12,118.11 168.66,118.11 E100.13 | v153.67,113.54 152.65,113.54 152.65,113.28 E103.6
  Bottom 0.254: v165.1,119.63 164.34,120.4 153.16,120.4 152.15,119.38 147.07,119.38 146.3,118.62 146.3,113.54 | 146.3,113.54 v153.67,113.54 | v156.72,68.33 155.7,69.34 147.57,69.34 145.29,71.63 145.29,113.54 146.3,113.54
FF10  (via drill 0.61)
  Top 0.254: 153.42,102.36 152.65,101.6 E104.2 | 153.42,102.36 153.92,102.87 153.92,103.63 157.23,103.63 157.99,104.39 161.04,104.39 162.31,103.12 E101.1 | v155.45,77.98 154.69,78.74 154.69,101.09 153.42,102.36
  Bottom 0.254: J10.2 160.78,73.91 164.59,73.91 164.59,76.2 163.83,76.96 161.29,76.96 160.78,76.45 FF10.1 159.26,76.45 157.73,77.98 v155.45,77.98
FF11  (via drill 0.61)
  Top 0.254: FF11.1 160.27,4.32 160.27,3.3 J11.2 159.26,2.29 158.75,2.29 158.24,1.78 156.72,1.78 v156.72,2.29 | v165.1,53.59 166.12,52.58 166.12,52.07 168.66,52.07 E121.13 | v153.67,47.5 152.65,47.5 152.65,47.24 E124.6
  Bottom 0.254: v165.1,53.59 164.34,54.36 153.16,54.36 152.15,53.34 147.07,53.34 146.3,52.58 146.3,47.5 | 146.3,47.5 v153.67,47.5 | v156.72,2.29 155.7,3.3 147.57,3.3 145.29,5.59 145.29,47.5 146.3,47.5
FF12  (via drill 0.61)
  Top 0.254: 153.42,36.32 152.65,35.56 E125.2 | 153.42,36.32 153.92,36.83 153.92,37.59 157.23,37.59 157.99,38.35 161.04,38.35 162.31,37.08 E122.1 | v155.45,11.94 154.69,12.7 154.69,35.05 153.42,36.32
  Bottom 0.254: J12.2 160.78,7.87 164.59,7.87 164.59,10.16 163.83,10.92 161.29,10.92 160.78,10.41 FF12.1 159.26,10.41 157.73,11.94 v155.45,11.94
GND  (via drill 0.61)
  Top 0.381: R3.1 72.14,54.1 72.14,50.55 71.37,49.78 E12.7 69.6,49.78 v68.83,50.55 | v81.03,54.36 81.03,49.78 E15.7 | v33.02,49.28 32,49.28 E3.7 | v41.91,49.28 42.93,49.28 E6.7 | v55.88,49.53 56.9,49.53 E9.7 | v14.99,50.8 13.97,50.8 U$1.T1 | E13.7 81.03,16.76 81.03,22.35 C14.2 | C17.2 92.71,22.35 92.71,16.76 E16.7 94.23,16.51 95.5,15.24 95.5,14.73 96.65,13.59 | 96.65,13.59 96.77,13.46 96.77,12.95 97.54,12.95 E19.11 | E1.7 30.23,16.76 30.23,22.35 C2.2 | E4.7 42.93,16.76 42.93,22.35 C5.2 42.93,23.37 40.89,25.4 40.89,31.5 42.93,33.53 | E7.7 57.15,16.76 57.15,22.35 C8.2 | E10.7 69.6,16.76 69.6,22.35 C11.2 | E2.7 30.48,33.27 30.48,38.86 C3.2 | 42.93,33.53 42.93,38.86 C6.2 | 42.93,33.53 42.93,33.27 E5.7 | E21.11 97.54,45.97 v96.52,45.97 96.27,45.97 96.27,48.26 95.25,49.28 94.23,49.28 E18.7 | E20.11 97.54,29.46 96.77,29.46 96.77,30.48 94.23,33.02 E17.7 92.46,33.27 92.46,38.86 C18.2 | E14.7 81.03,33.27 81.03,38.86 C15.2 | E8.7 57.15,33.27 57.15,38.86 C9.2 | E11.7 69.6,33.27 69.6,38.86 C12.2 | v96.52,13.46 96.65,13.59
  Bottom 0.381: 90.42,7.62 91.19,7.62 92.2,6.6 C16.2 93.22,6.1 98.55,6.1 C19.2 | 90.42,7.62 82.8,7.62 81.79,6.6 C13.2 80.77,6.6 80.52,6.86 77.47,6.86 76.71,7.62 68.58,7.62 68.45,7.49 | 31.88,7.49 32,7.62 41.66,7.62 41.78,7.49 | 31.88,7.49 30.99,6.6 C1.2 | 41.78,7.49 42.67,6.6 C4.2 | 55.75,7.49 55.63,7.62 41.91,7.62 41.78,7.49 | 55.75,7.49 56.64,6.6 C7.2 | 68.45,7.49 68.33,7.62 55.88,7.62 55.75,7.49 | 68.45,7.49 69.34,6.6 C10.2 | U$1.C2 13.97,9.65 16,7.62 31.75,7.62 31.88,7.49 | v81.03,54.36 72.9,54.36 R3.1 72.14,55.12 72.14,56.64 R1.1 | v14.99,50.8 16,49.78 32.51,49.78 32.77,49.53 v33.02,49.28 v41.91,49.28 42.16,49.53 v55.88,49.53 56.13,49.78 56.64,50.29 68.58,50.29 v68.83,50.55 69.09,50.29 69.34,50.04 79.25,50.04 79.5,49.78 91.44,49.78 95,46.23 96.27,46.23 v96.52,45.97 96.52,42.42 97.54,42.42 98.81,41.15 98.81,39.88 C21.2 98.55,39.12 93.22,39.12 C18.2 92.2,39.62 91.19,40.64 80.01,40.64 79.88,40.51 | C20.2 98.55,22.61 93.22,22.61 C17.2 92.2,23.11 91.19,24.13 82.8,24.13 81.79,23.11 C14.2 80.77,23.11 79.76,24.13 74.42,24.13 73.41,23.11 70.36,23.11 C11.2 69.34,23.11 68.33,24.13 58.67,24.13 57.66,23.11 C8.2 56.64,23.11 55.12,23.11 54.1,24.13 44.7,24.13 43.69,23.11 C5.2 42.67,23.11 41.66,24.13 37.59,24.13 37.08,23.62 31.5,23.62 30.99,23.11 C2.2 | C3.2 30.99,39.62 32,40.64 41.66,40.64 42.67,39.62 C6.2 43.69,39.62 44.2,40.13 51.05,40.13 51.56,40.64 58.42,40.64 58.55,40.51 | 58.55,40.51 58.67,40.64 68.33,40.64 68.45,40.51 | 58.55,40.51 57.66,39.62 C9.2 | 68.45,40.51 69.34,39.62 C12.2 | 79.88,40.51 79.76,40.64 68.58,40.64 68.45,40.51 | 79.88,40.51 80.77,39.62 C15.2
  Bottom 0.381: 90.42,7.62 90.42,10.92 93.98,10.92 v96.52,13.46
  pour Bottom: 16.51,0 16.51,62.23 127,62.23 127,0
  pour Top: 16.51,0 16.51,62.23 127,62.23 127,0
GND1  (via drill 0.61)
  Top 0.381: R8.1 72.14,120.14 72.14,116.59 71.37,115.82 E30.7 69.6,115.82 v68.83,116.59 | v81.03,120.4 81.03,115.82 E33.7 | v33.02,115.32 32,115.32 E36.7 | v41.91,115.32 42.93,115.32 E23.7 | v55.88,115.57 56.9,115.57 E27.7 | v14.99,116.84 13.97,116.84 U$6.T1 | E31.7 81.03,82.8 81.03,88.39 C34.2 | C38.2 92.71,88.39 92.71,82.8 E37.7 94.23,82.55 95.5,81.28 95.5,80.77 96.65,79.63 | 96.65,79.63 96.77,79.5 96.77,78.99 97.54,78.99 E40.11 | E34.7 30.23,82.8 30.23,88.39 C23.2 | E22.7 42.93,82.8 42.93,88.39 C26.2 42.93,89.41 40.89,91.44 40.89,97.54 42.93,99.57 | E25.7 57.15,82.8 57.15,88.39 C28.2 | E28.7 69.6,82.8 69.6,88.39 C31.2 | E35.7 30.48,99.31 30.48,104.9 C24.2 | 42.93,99.57 42.93,104.9 C36.2 | 42.93,99.57 42.93,99.31 E24.7 | E42.11 97.54,112.01 v96.52,112.01 96.27,112.01 96.27,114.3 95.25,115.32 94.23,115.32 E39.7 | E41.11 97.54,95.5 96.77,95.5 96.77,96.52 94.23,99.06 E38.7 92.46,99.31 92.46,104.9 C39.2 | E32.7 81.03,99.31 81.03,104.9 C35.2 | E26.7 57.15,99.31 57.15,104.9 C29.2 | E29.7 69.6,99.31 69.6,104.9 C32.2 | v96.52,79.5 96.65,79.63
  Bottom 0.381: 90.42,73.66 91.19,73.66 92.2,72.64 C37.2 93.22,72.14 98.55,72.14 C40.2 | 90.42,73.66 82.8,73.66 81.79,72.64 C33.2 80.77,72.64 80.52,72.9 77.47,72.9 76.71,73.66 68.58,73.66 68.45,73.53 | 31.88,73.53 32,73.66 41.66,73.66 41.78,73.53 | 31.88,73.53 30.99,72.64 C22.2 | 41.78,73.53 42.67,72.64 C25.2 | 55.75,73.53 55.63,73.66 41.91,73.66 41.78,73.53 | 55.75,73.53 56.64,72.64 C27.2 | 68.45,73.53 68.33,73.66 55.88,73.66 55.75,73.53 | 68.45,73.53 69.34,72.64 C30.2 | U$6.C2 13.97,75.69 16,73.66 31.75,73.66 31.88,73.53 | v81.03,120.4 72.9,120.4 R8.1 72.14,121.16 72.14,122.68 R5.1 | v14.99,116.84 16,115.82 32.51,115.82 32.77,115.57 v33.02,115.32 v41.91,115.32 42.16,115.57 v55.88,115.57 56.13,115.82 56.64,116.33 68.58,116.33 v68.83,116.59 69.09,116.33 69.34,116.08 79.25,116.08 79.5,115.82 91.44,115.82 95,112.27 96.27,112.27 v96.52,112.01 96.52,108.46 97.54,108.46 98.81,107.19 98.81,105.92 C42.2 98.55,105.16 93.22,105.16 C39.2 92.2,105.66 91.19,106.68 80.01,106.68 79.88,106.55 | C41.2 98.55,88.65 93.22,88.65 C38.2 92.2,89.15 91.19,90.17 82.8,90.17 81.79,89.15 C34.2 80.77,89.15 79.76,90.17 74.42,90.17 73.41,89.15 70.36,89.15 C31.2 69.34,89.15 68.33,90.17 58.67,90.17 57.66,89.15 C28.2 56.64,89.15 55.12,89.15 54.1,90.17 44.7,90.17 43.69,89.15 C26.2 42.67,89.15 41.66,90.17 37.59,90.17 37.08,89.66 31.5,89.66 30.99,89.15 C23.2 | C24.2 30.99,105.66 32,106.68 41.66,106.68 42.67,105.66 C36.2 43.69,105.66 44.2,106.17 51.05,106.17 51.56,106.68 58.42,106.68 58.55,106.55 | 58.55,106.55 58.67,106.68 68.33,106.68 68.45,106.55 | 58.55,106.55 57.66,105.66 C29.2
  Bottom 0.381: 68.45,106.55 69.34,105.66 C32.2 | 79.88,106.55 79.76,106.68 68.58,106.68 68.45,106.55 | 79.88,106.55 80.77,105.66 C35.2 | 90.42,73.66 90.42,76.96 93.98,76.96 v96.52,79.5
  pour Bottom: 16.51,66.04 16.51,128.27 127,128.27 127,66.04
  pour Top: 16.51,66.04 16.51,128.27 127,128.27 127,66.04
GND2  (via drill 0.61)
  Top 0.381: R12.1 72.14,186.18 72.14,182.63 71.37,181.86 E51.7 69.6,181.86 v68.83,182.63 | v81.03,186.44 81.03,181.86 E54.7 | v33.02,181.36 32,181.36 E57.7 | v41.91,181.36 42.93,181.36 E44.7 | v55.88,181.61 56.9,181.61 E48.7 | v14.99,182.88 13.97,182.88 U$9.T1 | E52.7 81.03,148.84 81.03,154.43 C55.2 | C59.2 92.71,154.43 92.71,148.84 E58.7 94.23,148.59 95.5,147.32 95.5,146.81 96.65,145.67 | 96.65,145.67 96.77,145.54 96.77,145.03 97.54,145.03 E61.11 | E55.7 30.23,148.84 30.23,154.43 C44.2 | E43.7 42.93,148.84 42.93,154.43 C47.2 42.93,155.45 40.89,157.48 40.89,163.58 42.93,165.61 | E46.7 57.15,148.84 57.15,154.43 C49.2 | E49.7 69.6,148.84 69.6,154.43 C52.2 | E56.7 30.48,165.35 30.48,170.94 C45.2 | 42.93,165.61 42.93,170.94 C57.2 | 42.93,165.61 42.93,165.35 E45.7 | E63.11 97.54,178.05 v96.52,178.05 96.27,178.05 96.27,180.34 95.25,181.36 94.23,181.36 E60.7 | E62.11 97.54,161.54 96.77,161.54 96.77,162.56 94.23,165.1 E59.7 92.46,165.35 92.46,170.94 C60.2 | E53.7 81.03,165.35 81.03,170.94 C56.2 | E47.7 57.15,165.35 57.15,170.94 C50.2 | E50.7 69.6,165.35 69.6,170.94 C53.2 | 96.65,145.67 v96.52,145.54
  Bottom 0.381: 90.42,139.7 91.19,139.7 92.2,138.68 C58.2 93.22,138.18 98.55,138.18 C61.2 | 90.42,139.7 82.8,139.7 81.79,138.68 C54.2 80.77,138.68 80.52,138.94 77.47,138.94 76.71,139.7 68.58,139.7 68.45,139.57 | 31.88,139.57 32,139.7 41.66,139.7 41.78,139.57 | 31.88,139.57 30.99,138.68 C43.2 | 41.78,139.57 42.67,138.68 C46.2 | 55.75,139.57 55.63,139.7 41.91,139.7 41.78,139.57 | 55.75,139.57 56.64,138.68 C48.2 | 68.45,139.57 68.33,139.7 55.88,139.7 55.75,139.57 | 68.45,139.57 69.34,138.68 C51.2 | U$9.C2 13.97,141.73 16,139.7 31.75,139.7 31.88,139.57 | v81.03,186.44 72.9,186.44 R12.1 72.14,187.2 72.14,188.72 R9.1 | v14.99,182.88 16,181.86 32.51,181.86 32.77,181.61 v33.02,181.36 v41.91,181.36 42.16,181.61 v55.88,181.61 56.13,181.86 56.64,182.37 68.58,182.37 v68.83,182.63 69.09,182.37 69.34,182.12 79.25,182.12 79.5,181.86 91.44,181.86 95,178.31 96.27,178.31 v96.52,178.05 96.52,174.5 97.54,174.5 98.81,173.23 98.81,171.96 C63.2 98.55,171.2 93.22,171.2 C60.2 92.2,171.7 91.19,172.72 80.01,172.72 79.88,172.59 | C62.2 98.55,154.69 93.22,154.69 C59.2 92.2,155.19 91.19,156.21 82.8,156.21 81.79,155.19 C55.2 80.77,155.19 79.76,156.21 74.42,156.21 73.41,155.19 70.36,155.19 C52.2 69.34,155.19 68.33,156.21 58.67,156.21 57.66,155.19 C49.2 56.64,155.19 55.12,155.19 54.1,156.21 44.7,156.21 43.69,155.19 C47.2 42.67,155.19 41.66,156.21 37.59,156.21 37.08,155.7 31.5,155.7 30.99,155.19 C44.2 | C45.2 30.99,171.7 32,172.72 41.66,172.72 42.67,171.7 C57.2 43.69,171.7 44.2,172.21 51.05,172.21 51.56,172.72 58.42,172.72 58.55,172.59 | 58.55,172.59 58.67,172.72 68.33,172.72 68.45,172.59
  Bottom 0.381: 58.55,172.59 57.66,171.7 C50.2 | 68.45,172.59 69.34,171.7 C53.2 | 79.88,172.59 79.76,172.72 68.58,172.72 68.45,172.59 | 79.88,172.59 80.77,171.7 C56.2 | 90.42,139.7 90.42,143 93.98,143 v96.52,145.54
  pour Bottom: 16.51,132.08 16.51,194.31 127,194.31 127,132.08
  pour Top: 16.51,132.08 16.51,194.31 127,194.31 127,132.08
GND3  (via drill 0.61)
  Top 0.381: R16.1 184.4,140.21 184.4,143.76 185.17,144.53 E72.7 186.94,144.53 v187.71,143.76 | v175.51,139.95 175.51,144.53 E75.7 | v223.52,145.03 224.54,145.03 E78.7 | v214.63,145.03 213.61,145.03 E65.7 | v200.66,144.78 199.64,144.78 E69.7 | v241.55,143.51 242.57,143.51 U$12.T1 | E73.7 175.51,177.55 175.51,171.96 C76.2 | C80.2 163.83,171.96 163.83,177.55 E79.7 162.31,177.8 161.04,179.07 161.04,179.58 159.89,180.72 | 159.89,180.72 159.77,180.85 159.77,181.36 159,181.36 E82.11 | E76.7 226.31,177.55 226.31,171.96 C65.2 | E64.7 213.61,177.55 213.61,171.96 C68.2 213.61,170.94 215.65,168.91 215.65,162.81 213.61,160.78 | E67.7 199.39,177.55 199.39,171.96 C70.2 | E70.7 186.94,177.55 186.94,171.96 C73.2 | E77.7 226.06,161.04 226.06,155.45 C66.2 | 213.61,160.78 213.61,155.45 C78.2 | 213.61,160.78 213.61,161.04 E66.7 | E84.11 159,148.34 v160.02,148.34 160.27,148.34 160.27,146.05 161.29,145.03 162.31,145.03 E81.7 | E83.11 159,164.85 159.77,164.85 159.77,163.83 162.31,161.29 E80.7 164.08,161.04 164.08,155.45 C81.2 | E74.7 175.51,161.04 175.51,155.45 C77.2 | E68.7 199.39,161.04 199.39,155.45 C71.2 | E71.7 186.94,161.04 186.94,155.45 C74.2 | 159.89,180.72 v160.02,180.85
  Bottom 0.381: 166.12,186.69 165.35,186.69 164.34,187.71 C79.2 163.32,188.21 157.99,188.21 C82.2 | 166.12,186.69 173.74,186.69 174.75,187.71 C75.2 175.77,187.71 176.02,187.45 179.07,187.45 179.83,186.69 187.96,186.69 188.09,186.82 | 224.66,186.82 224.54,186.69 214.88,186.69 214.76,186.82 | 224.66,186.82 225.55,187.71 C64.2 | 214.76,186.82 213.87,187.71 C67.2 | 200.79,186.82 200.91,186.69 214.63,186.69 214.76,186.82 | 200.79,186.82 199.9,187.71 C69.2 | 188.09,186.82 188.21,186.69 200.66,186.69 200.79,186.82 | 188.09,186.82 187.2,187.71 C72.2 | U$12.C2 242.57,184.66 240.54,186.69 224.79,186.69 224.66,186.82 | v175.51,139.95 183.64,139.95 R16.1 184.4,139.19 184.4,137.67 R13.1 | v241.55,143.51 240.54,144.53 224.03,144.53 223.77,144.78 v223.52,145.03 v214.63,145.03 214.38,144.78 v200.66,144.78 200.41,144.53 199.9,144.02 187.96,144.02 v187.71,143.76 187.45,144.02 187.2,144.27 177.29,144.27 177.04,144.53 165.1,144.53 161.54,148.08 160.27,148.08 v160.02,148.34 160.02,151.89 159,151.89 157.73,153.16 157.73,154.43 C84.2 157.99,155.19 163.32,155.19 C81.2 164.34,154.69 165.35,153.67 176.53,153.67 176.66,153.8 | C83.2 157.99,171.7 163.32,171.7 C80.2 164.34,171.2 165.35,170.18 173.74,170.18 174.75,171.2 C76.2 175.77,171.2 176.78,170.18 182.12,170.18 183.13,171.2 186.18,171.2 C73.2 187.2,171.2 188.21,170.18 197.87,170.18 198.88,171.2 C70.2 199.9,171.2 201.42,171.2 202.44,170.18 211.84,170.18 212.85,171.2 C68.2 213.87,171.2 214.88,170.18 218.95,170.18 219.46,170.69 225.04,170.69 225.55,171.2 C65.2 | C66.2 225.55,154.69 224.54,153.67 214.88,153.67 213.87,154.69 C78.2 212.85,154.69 212.34,154.18 205.49,154.18 204.98,153.67 198.12,153.67 197.99,153.8
  Bottom 0.381: 197.99,153.8 197.87,153.67 188.21,153.67 188.09,153.8 | 197.99,153.8 198.88,154.69 C71.2 | 188.09,153.8 187.2,154.69 C74.2 | 176.66,153.8 176.78,153.67 187.96,153.67 188.09,153.8 | 176.66,153.8 175.77,154.69 C77.2 | 166.12,186.69 166.12,183.39 162.56,183.39 v160.02,180.85
  pour Bottom: 240.03,194.31 240.03,132.08 129.54,132.08 129.54,194.31
  pour Top: 240.03,194.31 240.03,132.08 129.54,132.08 129.54,194.31
GND4  (via drill 0.61)
  Top 0.381: R20.1 184.4,74.17 184.4,77.72 185.17,78.49 E93.7 186.94,78.49 v187.71,77.72 | v175.51,73.91 175.51,78.49 E96.7 | v223.52,78.99 224.54,78.99 E99.7 | v214.63,78.99 213.61,78.99 E86.7 | v200.66,78.74 199.64,78.74 E90.7 | v241.55,77.47 242.57,77.47 U$15.T1 | E94.7 175.51,111.51 175.51,105.92 C97.2 | C101.2 163.83,105.92 163.83,111.51 E100.7 162.31,111.76 161.04,113.03 161.04,113.54 159.89,114.68 | 159.89,114.68 159.77,114.81 159.77,115.32 159,115.32 E103.11 | E97.7 226.31,111.51 226.31,105.92 C86.2 | E85.7 213.61,111.51 213.61,105.92 C89.2 213.61,104.9 215.65,102.87 215.65,96.77 213.61,94.74 | E88.7 199.39,111.51 199.39,105.92 C91.2 | E91.7 186.94,111.51 186.94,105.92 C94.2 | E98.7 226.06,95 226.06,89.41 C87.2 | 213.61,94.74 213.61,89.41 C99.2 | 213.61,94.74 213.61,95 E87.7 | E105.11 159,82.3 v160.02,82.3 160.27,82.3 160.27,80.01 161.29,78.99 162.31,78.99 E102.7 | E104.11 159,98.81 159.77,98.81 159.77,97.79 162.31,95.25 E101.7 164.08,95 164.08,89.41 C102.2 | E95.7 175.51,95 175.51,89.41 C98.2 | E89.7 199.39,95 199.39,89.41 C92.2 | E92.7 186.94,95 186.94,89.41 C95.2 | 159.89,114.68 v160.02,114.81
